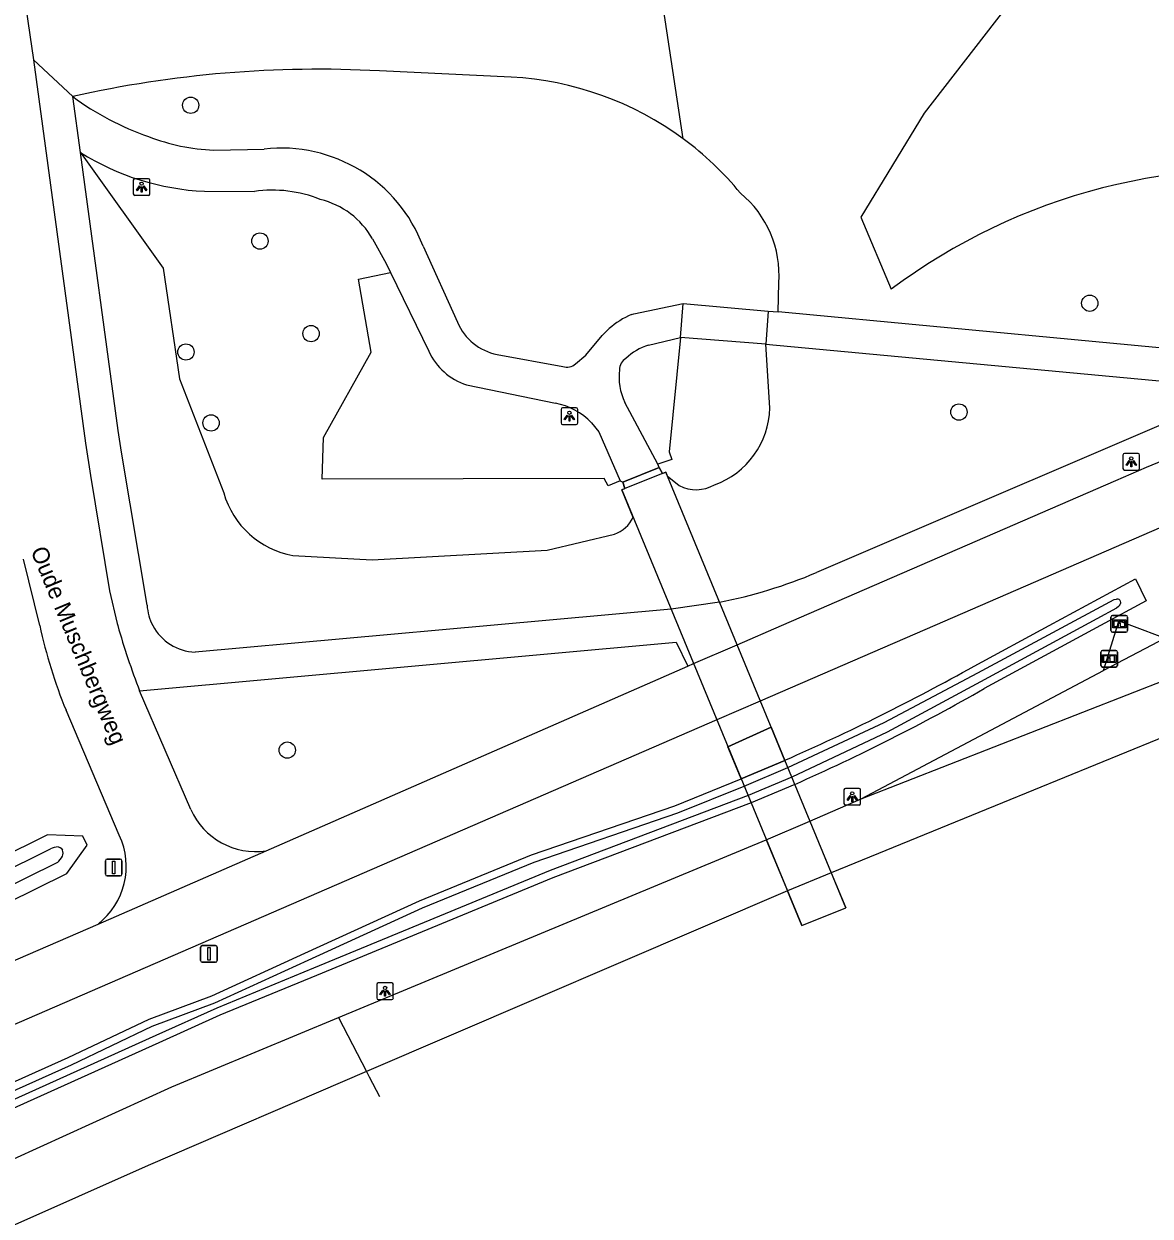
# Model space of a CAD drawing. Extents: x 162722 to 165099, y 384721 to 386283.
# Drawn here: x 164182.3 to 164249.8, y 384964.6 to 385036.1 of the extents above; entities that cross this region are included whole.
import ezdxf

# ---------------------------------------------------------------- set-up
doc = ezdxf.new("R2010")
doc.units = 0
for name, color, linetype in [('IMGEO_Berm_groen', 7, 'Continuous'), ('IMGEO_Boom', 7, 'Continuous'), ('IMGEO_Dek', 7, 'Continuous'), ('IMGEO_Fietspad_gesloten', 7, 'Continuous'), ('IMGEO_Groenvoorziening', 7, 'Continuous'), ('IMGEO_Informatiebord', 7, 'Continuous'), ('IMGEO_Lichtpunt', 7, 'Continuous'), ('IMGEO_Loofbos', 7, 'Continuous'), ('IMGEO_Muur', 7, 'Continuous'), ('IMGEO_Oever', 7, 'Continuous'), ('IMGEO_Openbare_ruimte_label', 7, 'Continuous'), ('IMGEO_OVBaan_open', 7, 'Continuous'), ('IMGEO_Pijler', 7, 'Continuous'), ('IMGEO_Rijbaan_lokaal_open', 7, 'Continuous'), ('IMGEO_Rijbaan_regionaal_gesloten', 7, 'Continuous'), ('IMGEO_Verkeersbordpaal', 7, 'Continuous'), ('IMGEO_Voetpad_gesloten', 7, 'Continuous'), ('IMGEO_Voetpad_open', 7, 'Continuous'), ('IMGEO_Waterloop', 7, 'Continuous')]:
    doc.layers.add(name, color=color, linetype=linetype)

msp = doc.modelspace()

# ---------------------------------------------------------------- linework, layer by layer
at = {"layer": 'IMGEO_Berm_groen'}
for points in [[(164239.27, 384997.566), (164243.767, 385000), (164248.945, 385002.803), (164249.58, 385001.482), (164246.849, 385000), (164239.88, 384996.219)], [(164225.31, 384990.805), (164224.511, 384992.738), (164227.098, 384993.913), (164227.922, 384991.919)], [(163807.895, 384780.491), (163820.578, 384786.077), (163833.812, 384792.708), (163845.028, 384798.673), (163914.436, 384836.893), (163949.636, 384856.503), (163973.819, 384869.778), (164000, 384884.149), (164013.236, 384891.063), (164022.225, 384895.944), (164051.682, 384911.299), (164065.065, 384918.062), (164110.825, 384940.537), (164141.781, 384954.8), (164143.407, 384955.639), (164157.246, 384961.665), (164184.977, 384974.098), (164189.827, 384976.411), (164193.585, 384977.81), (164199.165, 384980.364), (164206.029, 384983.505), (164212.733, 384986.251), (164221.342, 384989.201), (164225.31, 384990.805)], [(164228.517, 384990.478), (164225.9, 384989.377), (164214.028, 384984.88), (164199.858, 384979.031), (164194.068, 384976.641), (164190.414, 384974.994), (164164.458, 384963.293), (164143.813, 384954.267), (164142.441, 384953.403), (164125.834, 384945.724), (164092.923, 384929.936), (164061.637, 384914.529), (164036.116, 384901.563), (164011.738, 384888.674), (164000, 384882.305), (163974.591, 384868.517), (163970.141, 384866.102), (163854.543, 384802.202), (163834.335, 384791.252), (163820.765, 384784.53), (163800.899, 384775.69)], [(164184.89, 384985.145), (164186.107, 384986.836), (164185.859, 384987.374), (164183.725, 384987.45), (164141.087, 384966.275), (164139.999, 384964.462), (164140.35, 384963.895), (164141.803, 384963.834), (164184.89, 384985.145)]]:
    msp.add_lwpolyline(points, dxfattribs=at)
for centre, radius, start, end in [((164174.959, 385112.576), 131.769, 293.69908, 299.2127), ((164178.949, 385102.703), 122.685, 293.83045, 299.77868)]:
    msp.add_arc(centre, radius, start, end, dxfattribs=at)
at = {"layer": 'IMGEO_Boom'}
for centre in [(164192.314, 385031.187), (164196.467, 385023.047), (164246.205, 385019.322), (164199.528, 385017.501), (164192.031, 385016.396), (164238.36, 385012.797), (164193.537, 385012.146), (164198.104, 384992.531)]:
    msp.add_circle(centre, 0.489, dxfattribs=at)
at = {"layer": 'IMGEO_Dek'}
msp.add_lwpolyline([(164231.573, 384983.081), (164220.787, 385009.193), (164220.592, 385009.115), (164220.399, 385009.469), (164218.209, 385008.591), (164218.345, 385008.216), (164218.15, 385008.138), (164228.941, 384982.015)], close=True, dxfattribs=at)
at = {"layer": 'IMGEO_Fietspad_gesloten'}
for points in [[(164222.114, 384997.568), (164222.455, 384997.716), (164225.061, 384998.845), (164227.726, 385000), (164247.774, 385008.689), (164249.613, 385009.488), (164257.963, 385012.93)], [(164257.459, 385008.904), (164236.917, 385000), (164226.457, 384995.466), (164223.851, 384994.337), (164174.926, 384973.13), (164140.511, 384957.62), (164127.585, 384951.111)], [(164196.835, 384986.501), (164222.114, 384997.568)], [(163837.761, 384799.983), (163968.381, 384872.098), (163971.397, 384873.736), (164000, 384889.267), (164029.893, 384905.296), (164057.852, 384919.483), (164097.492, 384939.034), (164124.664, 384953.575), (164138.961, 384960.973), (164173.572, 384976.374), (164186.765, 384982.108)]]:
    msp.add_lwpolyline(points, dxfattribs=at)
at = {"layer": 'IMGEO_Groenvoorziening'}
for points in [[(164221.84, 385029.172), (164220.032, 385041.077)], [(164211.525, 385032.872), (164203.634, 385033.245)], [(164185.711, 385028.348), (164190.662, 385021.427), (164191.639, 385014.785), (164194.294, 385007.945)], [(164218.053, 385008.675), (164217.331, 385008.373), (164217.106, 385008.808), (164200.197, 385008.775), (164200.27, 385011.265), (164203.137, 385016.379), (164202.367, 385020.763), (164204.282, 385021.16)], [(164227.527, 385018.794), (164227.565, 385020.546)], [(164221.679, 385017.265), (164220.997, 385010.405), (164221.147, 385009.961), (164220.323, 385009.663)], [(164227.02, 385013.042), (164226.782, 385016.868)], [(164220.592, 385009.115), (164220.787, 385009.193), (164220.879, 385008.971), (164221.598, 385008.386)], [(164218.835, 385006.479), (164218.15, 385008.138), (164218.345, 385008.216)], [(164198.438, 385004.196), (164203.186, 385003.934), (164213.685, 385004.52), (164217.715, 385005.484)]]:
    msp.add_lwpolyline(points, dxfattribs=at)
for centre, radius, start, end in [((164199.962, 384966.414), 66.932, 86.85541, 102.70488), ((164210.515, 385013.828), 19.071, 53.56993, 86.96416), ((164210.536, 385013.848), 19.042, 39.33103, 53.58459), ((164221.255, 385021.022), 6.327, 355.68512, 50.67858), ((164222.002, 385013.152), 5.02, 289.81281, 358.739), ((164199.395, 385009.418), 5.309, 196.1099, 259.61998), ((164222.61, 385010.366), 2.223, 242.933, 299.46191), ((164217.099, 385007.305), 1.923, 288.68647, 334.54885)]:
    msp.add_arc(centre, radius, start, end, dxfattribs=at)
at = {"layer": 'IMGEO_Informatiebord'}
for p, q in [((164247.475, 384999.701), (164247.475, 385000.501)), ((164247.475, 385000.501), (164247.475, 384999.701)), ((164247.575, 385000.601), (164248.365, 385000.601)), ((164248.365, 385000.601), (164247.575, 385000.601)), ((164248.465, 385000.501), (164248.465, 384999.701)), ((164248.465, 384999.701), (164248.465, 385000.501)), ((164248.365, 384999.601), (164247.575, 384999.601)), ((164247.575, 384999.601), (164248.365, 384999.601)), ((164246.867, 384997.613), (164246.867, 384998.413)), ((164246.867, 384998.413), (164246.867, 384997.613)), ((164246.967, 384998.513), (164247.757, 384998.513)), ((164247.757, 384998.513), (164246.967, 384998.513)), ((164247.857, 384998.413), (164247.857, 384997.613)), ((164247.857, 384997.613), (164247.857, 384998.413)), ((164247.757, 384997.513), (164246.967, 384997.513)), ((164246.967, 384997.513), (164247.757, 384997.513))]:
    msp.add_line(p, q, dxfattribs=at)
for points in [[(164247.576, 385000.333), (164248.364, 385000.333), (164248.364, 384999.869), (164247.576, 384999.869), (164247.576, 385000.333)], [(164247.641, 385000.268), (164247.641, 384999.934), (164247.916, 384999.934), (164247.917, 385000.147), (164248.021, 385000.148), (164248.022, 384999.934), (164248.299, 384999.934), (164248.299, 385000.268), (164248.023, 385000.268), (164248.023, 385000.188), (164247.917, 385000.188), (164247.917, 385000.268), (164247.641, 385000.268)], [(164246.968, 384998.245), (164247.756, 384998.245), (164247.756, 384997.781), (164246.968, 384997.781), (164246.968, 384998.245)], [(164247.033, 384998.18), (164247.033, 384997.846), (164247.308, 384997.846), (164247.309, 384998.059), (164247.413, 384998.06), (164247.414, 384997.846), (164247.691, 384997.846), (164247.691, 384998.18), (164247.415, 384998.18), (164247.415, 384998.1), (164247.309, 384998.1), (164247.309, 384998.18), (164247.033, 384998.18)]]:
    msp.add_lwpolyline(points, dxfattribs=at)
for centre, start, end in [((164247.575, 385000.501), 90, 180), ((164247.575, 385000.501), 90, 180), ((164248.365, 385000.501), 0, 90), ((164248.365, 385000.501), 360, 90), ((164247.575, 384999.701), 180, 270), ((164247.575, 384999.701), 180, 270), ((164248.365, 384999.701), 270, 0), ((164248.365, 384999.701), 270, 0), ((164246.967, 384998.413), 90, 180), ((164246.967, 384998.413), 90, 180), ((164247.757, 384998.413), 0, 90), ((164247.757, 384998.413), 360, 90), ((164246.967, 384997.613), 180, 270), ((164246.967, 384997.613), 180, 270), ((164247.757, 384997.613), 270, 0), ((164247.757, 384997.613), 270, 0)]:
    msp.add_arc(centre, 0.1, start, end, dxfattribs=at)
at = {"layer": 'IMGEO_Lichtpunt'}
for p, q in [((164188.877, 385026.689), (164188.877, 385025.882)), ((164188.877, 385026.689), (164188.877, 385025.882)), ((164189.779, 385026.784), (164188.971, 385026.784)), ((164189.779, 385026.784), (164188.971, 385026.784)), ((164189.873, 385025.882), (164189.873, 385026.689)), ((164189.873, 385025.882), (164189.873, 385026.689)), ((164188.971, 385025.788), (164189.779, 385025.788)), ((164188.971, 385025.788), (164189.779, 385025.788)), ((164214.515, 385012.954), (164214.515, 385012.147)), ((164214.515, 385012.954), (164214.515, 385012.147)), ((164215.417, 385013.049), (164214.609, 385013.049)), ((164215.417, 385013.049), (164214.609, 385013.049)), ((164215.511, 385012.147), (164215.511, 385012.954)), ((164215.511, 385012.147), (164215.511, 385012.954)), ((164214.609, 385012.053), (164215.417, 385012.053)), ((164214.609, 385012.053), (164215.417, 385012.053)), ((164248.194, 385010.221), (164248.194, 385009.414)), ((164248.194, 385010.221), (164248.194, 385009.414)), ((164249.096, 385010.316), (164248.288, 385010.316)), ((164249.096, 385010.316), (164248.288, 385010.316)), ((164249.19, 385009.414), (164249.19, 385010.221)), ((164249.19, 385009.414), (164249.19, 385010.221)), ((164248.288, 385009.32), (164249.096, 385009.32)), ((164248.288, 385009.32), (164249.096, 385009.32)), ((164231.47, 384990.143), (164231.47, 384989.336)), ((164231.47, 384990.143), (164231.47, 384989.336)), ((164232.372, 384990.238), (164231.564, 384990.238)), ((164232.372, 384990.238), (164231.564, 384990.238)), ((164232.466, 384989.336), (164232.466, 384990.143)), ((164232.466, 384989.336), (164232.466, 384990.143)), ((164231.564, 384989.242), (164232.372, 384989.242)), ((164231.564, 384989.242), (164232.372, 384989.242)), ((164203.465, 384978.482), (164203.465, 384977.675)), ((164203.465, 384978.482), (164203.465, 384977.675)), ((164204.367, 384978.577), (164203.559, 384978.577)), ((164204.367, 384978.577), (164203.559, 384978.577)), ((164204.461, 384977.675), (164204.461, 384978.482)), ((164204.461, 384977.675), (164204.461, 384978.482)), ((164203.559, 384977.581), (164204.367, 384977.581)), ((164203.559, 384977.581), (164204.367, 384977.581))]:
    msp.add_line(p, q, dxfattribs=at)
for points in [[(164189.251, 385026.353), (164189.29, 385026.325), (164189.102, 385026.063), (164189.064, 385026.09), (164189.251, 385026.353)], [(164189.353, 385026.305), (164189.4, 385026.305), (164189.4, 385025.983), (164189.353, 385025.983), (164189.353, 385026.305)], [(164189.463, 385026.325), (164189.501, 385026.352), (164189.688, 385026.09), (164189.649, 385026.062), (164189.463, 385026.325)], [(164214.889, 385012.618), (164214.928, 385012.59), (164214.74, 385012.328), (164214.702, 385012.355), (164214.889, 385012.618)], [(164214.991, 385012.57), (164215.038, 385012.57), (164215.038, 385012.248), (164214.991, 385012.248), (164214.991, 385012.57)], [(164215.101, 385012.59), (164215.139, 385012.617), (164215.326, 385012.355), (164215.287, 385012.327), (164215.101, 385012.59)], [(164248.568, 385009.885), (164248.607, 385009.857), (164248.419, 385009.595), (164248.381, 385009.622), (164248.568, 385009.885)], [(164248.67, 385009.837), (164248.717, 385009.837), (164248.717, 385009.515), (164248.67, 385009.515), (164248.67, 385009.837)], [(164248.78, 385009.857), (164248.818, 385009.884), (164249.005, 385009.622), (164248.966, 385009.594), (164248.78, 385009.857)], [(164231.844, 384989.807), (164231.883, 384989.779), (164231.695, 384989.517), (164231.657, 384989.544), (164231.844, 384989.807)], [(164231.946, 384989.759), (164231.993, 384989.759), (164231.993, 384989.437), (164231.946, 384989.437), (164231.946, 384989.759)], [(164232.056, 384989.779), (164232.094, 384989.806), (164232.281, 384989.544), (164232.242, 384989.516), (164232.056, 384989.779)], [(164203.839, 384978.146), (164203.878, 384978.118), (164203.69, 384977.856), (164203.652, 384977.883), (164203.839, 384978.146)], [(164203.941, 384978.098), (164203.988, 384978.098), (164203.988, 384977.776), (164203.941, 384977.776), (164203.941, 384978.098)], [(164204.051, 384978.118), (164204.089, 384978.145), (164204.276, 384977.883), (164204.237, 384977.855), (164204.051, 384978.118)]]:
    msp.add_lwpolyline(points, dxfattribs=at)
for centre in [(164189.376, 385026.487), (164215.014, 385012.752), (164248.693, 385010.019), (164231.969, 384989.941), (164203.964, 384978.28)]:
    msp.add_circle(centre, 0.0994, dxfattribs=at)
for centre, start, end in [((164188.971, 385026.689), 90, 180), ((164188.971, 385026.689), 90, 180), ((164189.779, 385026.689), 0, 90), ((164189.779, 385026.689), 0, 90), ((164188.971, 385025.882), 180, 270), ((164188.971, 385025.882), 180, 270), ((164189.779, 385025.882), 270, 0), ((164189.779, 385025.882), 270, 360), ((164214.609, 385012.954), 90, 180), ((164214.609, 385012.954), 90, 180), ((164215.417, 385012.954), 0, 90), ((164215.417, 385012.954), 0, 90), ((164214.609, 385012.147), 180, 270), ((164214.609, 385012.147), 180, 270), ((164215.417, 385012.147), 270, 0), ((164215.417, 385012.147), 270, 360), ((164248.288, 385010.221), 90, 180), ((164248.288, 385010.221), 90, 180), ((164249.096, 385010.221), 0, 90), ((164249.096, 385010.221), 0, 90), ((164248.288, 385009.414), 180, 270), ((164248.288, 385009.414), 180, 270), ((164249.096, 385009.414), 270, 0), ((164249.096, 385009.414), 270, 360), ((164231.564, 384990.143), 90, 180), ((164231.564, 384990.143), 90, 180), ((164232.372, 384990.143), 0, 90), ((164232.372, 384990.143), 0, 90), ((164231.564, 384989.336), 180, 270), ((164231.564, 384989.336), 180, 270), ((164232.372, 384989.336), 270, 0), ((164232.372, 384989.336), 270, 360), ((164203.559, 384978.482), 90, 180), ((164203.559, 384978.482), 90, 180), ((164204.367, 384978.482), 0, 90), ((164204.367, 384978.482), 0, 90), ((164203.559, 384977.675), 180, 270), ((164203.559, 384977.675), 180, 270), ((164204.367, 384977.675), 270, 0), ((164204.367, 384977.675), 270, 360)]:
    msp.add_arc(centre, 0.0946, start, end, dxfattribs=at)
at = {"layer": 'IMGEO_Loofbos'}
msp.add_lwpolyline([(164220.032, 385041.077), (164237.993, 385048.254), (164241.082, 385047.874), (164242.945, 385039.353), (164236.278, 385030.716), (164232.482, 385024.48), (164234.296, 385020.153)], dxfattribs=at)
msp.add_arc((164255.899, 384991.351), 36.003, 81.86544, 126.87164, dxfattribs=at)
at = {"layer": 'IMGEO_Muur'}
for points in [[(164218.209, 385008.591), (164220.399, 385009.469)], [(164220.399, 385009.469), (164220.592, 385009.115)], [(164220.592, 385009.115), (164218.345, 385008.216)], [(164218.345, 385008.216), (164218.209, 385008.591)]]:
    msp.add_lwpolyline(points, dxfattribs=at)
at = {"layer": 'IMGEO_Oever'}
msp.add_lwpolyline([(164227.922, 384991.919), (164225.31, 384990.805)], dxfattribs=at)
at = {"layer": 'IMGEO_OVBaan_open'}
for points in [[(164232.508, 384989.603), (164259.079, 385000), (164262.419, 385001.307)], [(164250.731, 384999.252), (164247.035, 384997.295)], [(164232.508, 384989.603), (164247.035, 384997.295)]]:
    msp.add_lwpolyline(points, dxfattribs=at)
at = {"layer": 'IMGEO_Pijler'}
msp.add_lwpolyline([(164227.098, 384993.913), (164224.511, 384992.738), (164225.31, 384990.805), (164227.922, 384991.919)], close=True, dxfattribs=at)
at = {"layer": 'IMGEO_Rijbaan_lokaal_open'}
for points in [[(164182.344, 385037.749), (164182.887, 385033.916)], [(164182.887, 385033.916), (164186.008, 385010.939), (164186.302, 385008.984), (164187.455, 385002.075), (164187.912, 385000.116), (164187.944, 385000)], [(164183.266, 385000), (164182.287, 385003.976)], [(164192.319, 384988.97), (164189.254, 384996.082)], [(164188.037, 384987.425), (164184.844, 384994.922)], [(164186.765, 384982.108), (164196.835, 384986.501)]]:
    msp.add_lwpolyline(points, dxfattribs=at)
for centre, radius, start, end in [((164212.764, 385006.382), 30.18, 192.20868, 202.31682), ((164228.563, 385011.403), 42.189, 195.68124, 201.29391), ((164196.205, 384990.713), 4.259, 204.15637, 278.51076), ((164184.075, 384985.562), 4.378, 307.91124, 25.18045)]:
    msp.add_arc(centre, radius, start, end, dxfattribs=at)
at = {"layer": 'IMGEO_Rijbaan_regionaal_gesloten'}
for points in [[(164263.334, 384998.39), (164252.127, 384993.919), (164240.977, 384989.371), (164230.704, 384985.185)], [(164229.43, 384988.27), (164232.508, 384989.603)], [(164226.817, 384987.156), (164229.43, 384988.27)], [(164229.43, 384988.27), (164230.704, 384985.185)], [(164201.175, 384976.496), (164226.817, 384987.156)], [(164226.817, 384987.156), (164228.079, 384984.101)], [(164230.704, 384985.185), (164228.079, 384984.101)], [(164230.704, 384985.185), (164231.573, 384983.081)], [(164228.079, 384984.101), (164202.848, 384973.275)], [(164228.941, 384982.015), (164228.222, 384983.755), (164228.079, 384984.101)], [(163832.079, 384786.732), (163976.198, 384865.89), (163988.462, 384872.626), (164000, 384879.089), (164010.013, 384884.532), (164040.026, 384900.418), (164068.299, 384914.743), (164098.314, 384929.568), (164139.038, 384948.773), (164142.262, 384950.403), (164161.969, 384959.269), (164170.65, 384962.991), (164191.19, 384972.345), (164201.175, 384976.496)], [(164201.175, 384976.496), (164202.848, 384973.275)], [(164202.848, 384973.275), (164189.764, 384967.635), (164164.509, 384956.406), (164136.448, 384943.995), (164077.479, 384915.27), (164051.634, 384902.415), (163978.153, 384862.695), (163978.101, 384862.667), (163880.927, 384809.18), (163846.958, 384790.267), (163834.094, 384783.248)], [(164202.848, 384973.275), (164203.022, 384972.94), (164203.632, 384971.767)]]:
    msp.add_lwpolyline(points, dxfattribs=at)
at = {"layer": 'IMGEO_Verkeersbordpaal'}
for p, q in [((164187.201, 384985.095), (164187.201, 384985.895)), ((164187.201, 384985.895), (164187.201, 384985.095)), ((164187.301, 384985.995), (164188.091, 384985.995)), ((164188.091, 384985.995), (164187.301, 384985.995)), ((164188.191, 384985.895), (164188.191, 384985.095)), ((164188.191, 384985.095), (164188.191, 384985.895)), ((164188.091, 384984.995), (164187.301, 384984.995)), ((164187.301, 384984.995), (164188.091, 384984.995)), ((164193.013, 384980.817), (164193.803, 384980.817)), ((164193.803, 384980.817), (164193.013, 384980.817)), ((164192.913, 384979.917), (164192.913, 384980.717)), ((164192.913, 384980.717), (164192.913, 384979.917)), ((164193.903, 384980.717), (164193.903, 384979.917)), ((164193.903, 384979.917), (164193.903, 384980.717)), ((164193.803, 384979.817), (164193.013, 384979.817)), ((164193.013, 384979.817), (164193.803, 384979.817))]:
    msp.add_line(p, q, dxfattribs=at)
for points in [[(164187.621, 384985.87), (164187.771, 384985.87), (164187.771, 384985.12), (164187.621, 384985.12), (164187.621, 384985.87)], [(164193.333, 384980.692), (164193.483, 384980.692), (164193.483, 384979.942), (164193.333, 384979.942), (164193.333, 384980.692)]]:
    msp.add_lwpolyline(points, dxfattribs=at)
for centre, start, end in [((164187.301, 384985.895), 90, 180), ((164187.301, 384985.895), 90, 180), ((164188.091, 384985.895), 0, 90), ((164188.091, 384985.895), 360, 90), ((164187.301, 384985.095), 180, 270), ((164187.301, 384985.095), 180, 270), ((164188.091, 384985.095), 270, 0), ((164188.091, 384985.095), 270, 0), ((164193.013, 384980.717), 90, 180), ((164193.013, 384980.717), 90, 180), ((164193.803, 384980.717), 0, 90), ((164193.803, 384980.717), 360, 90), ((164193.013, 384979.917), 180, 270), ((164193.013, 384979.917), 180, 270), ((164193.803, 384979.917), 270, 0), ((164193.803, 384979.917), 270, 0)]:
    msp.add_arc(centre, 0.1, start, end, dxfattribs=at)
at = {"layer": 'IMGEO_Voetpad_gesloten'}
for points in [[(164221.679, 385017.265), (164221.836, 385019.299)], [(164221.836, 385019.299), (164226.918, 385018.851)], [(164226.918, 385018.851), (164226.782, 385016.868)], [(164226.782, 385016.868), (164221.679, 385017.265)]]:
    msp.add_lwpolyline(points, dxfattribs=at)
at = {"layer": 'IMGEO_Voetpad_open'}
for points in [[(164182.887, 385033.916), (164185.242, 385031.707)], [(164185.711, 385028.348), (164185.242, 385031.707)], [(164189.7, 385001.218), (164188.163, 385010.392), (164187.966, 385011.698), (164185.711, 385028.348)], [(164193.701, 385028.502), (164196.711, 385028.561)], [(164193.139, 385026.029), (164196.133, 385026.022)], [(164203.209, 385023.187), (164204.04, 385021.698), (164204.282, 385021.16)], [(164206.243, 385022.742), (164208.305, 385018.185)], [(164204.282, 385021.16), (164206.592, 385016.441)], [(164218.735, 385018.636), (164218.872, 385018.682), (164221.836, 385019.299)], [(164226.918, 385018.851), (164227.527, 385018.794)], [(164257.182, 385014.893), (164256.723, 385016.046), (164227.527, 385018.794)], [(164215.382, 385015.681), (164215.995, 385016.198), (164216.98, 385017.39), (164217.399, 385017.796)], [(164219.753, 385016.809), (164221.679, 385017.265)], [(164226.782, 385016.868), (164255.518, 385014.18)], [(164210.677, 385016.245), (164214.619, 385015.523)], [(164208.85, 385014.429), (164214.178, 385013.332)], [(164255.518, 385014.18), (164229.825, 385003.177)], [(164220.323, 385009.663), (164218.329, 385013.374)], [(164216.337, 385012.144), (164216.778, 385011.601), (164218.053, 385008.675)], [(164220.399, 385009.469), (164220.323, 385009.663)], [(164218.053, 385008.675), (164218.209, 385008.591)], [(164224.007, 385001.397), (164221.107, 385000.979), (164210.287, 385000), (164192.581, 384998.398)], [(164247.035, 384997.295), (164247.859, 385000), (164247.944, 385000.279), (164248.701, 385000), (164250.731, 384999.252)], [(164189.254, 384996.082), (164221.419, 384999.011), (164222.114, 384997.568)]]:
    msp.add_lwpolyline(points, dxfattribs=at)
for centre, radius, start, end in [((164195.236, 385045.18), 16.775, 233.43401, 251.07484), ((164194.098, 385040.238), 11.743, 248.50528, 268.0636), ((164197.734, 385019.521), 9.098, 20.73658, 96.45779), ((164193.869, 385041.422), 15.411, 238.03771, 267.28587), ((164197.212, 385018.447), 7.651, 67.97465, 98.10409), ((164198.931, 385020.756), 4.92, 29.60861, 76.48765), ((164220.476, 385014.384), 4.595, 112.27048, 132.04817), ((164211.314, 385019.443), 3.261, 202.69816, 258.74407), ((164220.782, 385013.527), 3.44, 107.41241, 133.7632), ((164210.018, 385018.013), 3.77, 204.6493, 251.94517), ((164218.822, 385015.316), 0.811, 121.11406, 179.0344), ((164214.848, 385016.338), 0.846, 254.28559, 309.11302), ((164221.645, 385014.917), 3.657, 173.5147, 204.95364), ((164213.349, 385009.27), 4.146, 43.8898, 78.46621), ((164218.363, 385030.243), 29.393, 281.07064, 292.95203), ((164192.699, 385001.412), 3.005, 183.6966, 208.02016), ((164192.712, 385001.412), 3.017, 207.91035, 267.50775)]:
    msp.add_arc(centre, radius, start, end, dxfattribs=at)
at = {"layer": 'IMGEO_Waterloop'}
for points in [[(164051.894, 384910.885), (164065.272, 384917.646), (164111.025, 384940.117), (164141.985, 384954.382), (164143.607, 384955.219), (164157.434, 384961.24), (164185.172, 384973.676), (164190.008, 384975.983), (164193.763, 384977.38), (164199.358, 384979.941), (164206.214, 384983.078), (164212.897, 384985.816), (164221.505, 384988.765), (164225.487, 384990.375), (164228.1, 384991.49), (164233.871, 384994.19), (164239.489, 384997.156), (164243.988, 384999.591), (164247.662, 385001.561)], [(164247.662, 385001.561), (164247.803, 385001.583)], [(164248.007, 385001.522), (164248.034, 385001.489), (164248.054, 385001.367), (164248.044, 385001.322)], [(164247.925, 385001.148), (164247.808, 385001.049), (164246.627, 385000.409), (164239.659, 384996.628), (164234.063, 384993.616), (164228.34, 384990.908), (164225.722, 384989.807), (164213.857, 384985.312), (164199.681, 384979.461), (164193.884, 384977.068), (164190.223, 384975.418), (164164.269, 384963.718), (164143.595, 384954.679), (164142.219, 384953.812), (164125.636, 384946.145), (164092.72, 384930.354), (164061.429, 384914.945), (164035.902, 384901.976)], [(164141.534, 384965.562), (164141.675, 384965.638), (164183.906, 384986.611)], [(164184.38, 384986.727), (164184.495, 384986.703), (164184.561, 384986.664), (164184.641, 384986.539)], [(164184.335, 384985.799), (164141.803, 384964.764)]]:
    msp.add_lwpolyline(points, dxfattribs=at)
for centre, radius, start, end in [((164247.822, 385001.276), 0.308, 53.11048, 93.59413), ((164247.626, 385001.48), 0.447, 311.99366, 339.26926), ((164184.404, 384985.604), 1.123, 91.20454, 116.29841), ((164184.127, 384986.374), 0.54, 338.39297, 17.83066), ((164183.561, 384986.707), 1.193, 310.43674, 333.51849)]:
    msp.add_arc(centre, radius, start, end, dxfattribs=at)

# ---------------------------------------------------------------- texts
at = {"layer": 'IMGEO_Openbare_ruimte_label'}
msp.add_text('Oude Muschbergweg', height=1, rotation=292.6419, dxfattribs=at).set_placement((164182.703, 385004.486))

doc.saveas('drawing.dxf')
